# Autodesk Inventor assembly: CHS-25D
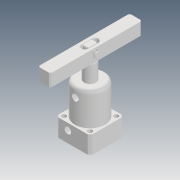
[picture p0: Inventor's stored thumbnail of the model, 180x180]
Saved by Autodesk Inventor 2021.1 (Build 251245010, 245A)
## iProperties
Created: 2019-04
Part Number: CHS-25D
Description: STEP AP203
Document SubType Name: Assembly
Designer: user
Title: chs-25d_asm.STEP
Revision Number: ÈÎºÎ
Sending System: SolidWorks 2017
Preprocessor: SwSTEP 2.0
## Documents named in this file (6)
- D:\Vault_2016\Projekty\Clamptek\Hydraulic\CHS\CHS-25\Inventor\CHS-25D\CHS-25D.iam
- D:\Vault_2016\Projekty\Clamptek\Hydraulic\CHS\CHS-25\Inventor\CHS-25D\CHS-25D-01.ipt
- D:\Vault_2016\Projekty\Clamptek\Hydraulic\CHS\CHS-25\Inventor\CHS-25D\CHS-25-03.ipt
- D:\Vault_2016\Projekty\Clamptek\Hydraulic\CHS\CHS-25\Inventor\CHS-25D\Xiao.ipt
- D:\Vault_2016\Projekty\Clamptek\Hydraulic\CHS\CHS-25\Inventor\CHS-25D\CHS-25D-02_1.ipt
- D:\Vault_2016\Projekty\Clamptek\Hydraulic\CHS\CHS-25\Inventor\CHS-25D\Öá8µ²È¦.ipt
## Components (6 placed, 6 different names)
1. CHS-25D-01_1
2. CHS-25-03_2
3. Xiao_3
4. CHS-25D-02_1_4
5. Öá8µ²È¦_5
6. Öá8µ²È¦_6
